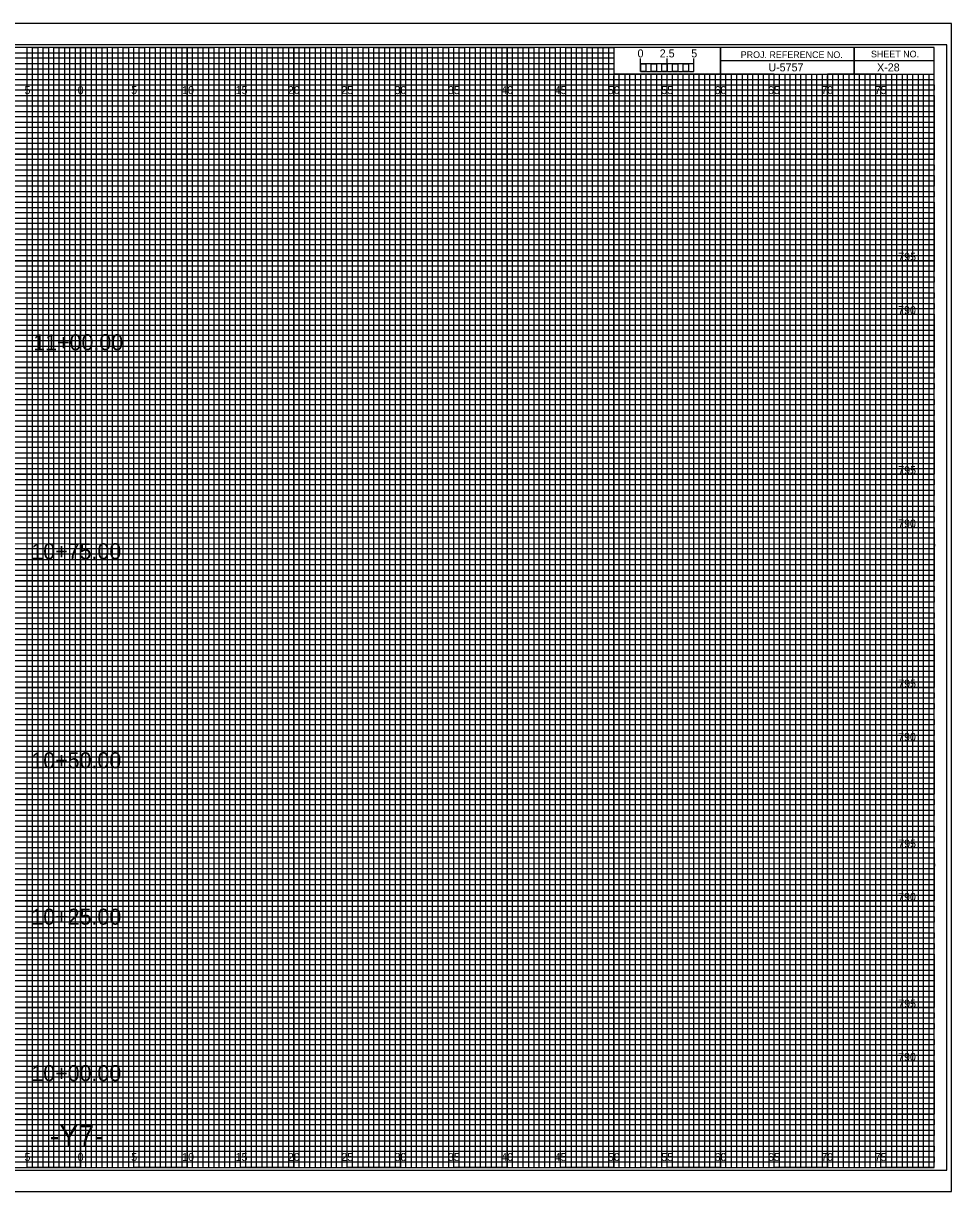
# Model space of a CAD drawing. Extents: x -7 to 162, y -2 to 107.
# Drawn here: x 74.6 to 161.7, y -2.3 to 107.3 of the extents above; entities that cross this region are included whole.
import ezdxf

# ---------------------------------------------------------------- set-up
doc = ezdxf.new("R2010")
doc.units = 0
for name, color, linetype in [('Exist Cross Section Cell', 7, 'Continuous'), ('Exist XS Center Line Elevation Label', 7, 'Continuous'), ('Prop CMT Pvmt Course 2 Wedge', 7, 'Continuous'), ('Prop XS Alignment Label', 7, 'Continuous'), ('Prop XS Bar Scale Labels', 7, 'Continuous'), ('Prop XS Elevation Labels', 7, 'Continuous'), ('Prop XS Hydro Elevations', 7, 'Continuous'), ('Prop XS Project Number', 7, 'Continuous'), ('Prop XS SE Text', 7, 'Continuous'), ('Prop XS Sheet Number', 7, 'Continuous'), ('Prop XS Side Slope Text', 7, 'Continuous'), ('Prop XS Station Labels', 7, 'Continuous'), ('Sheet Cross Section Scale CELL', 7, 'Continuous'), ('Sheet Cutting Line CELL', 7, 'Continuous'), ('Sheet DOT Grid CELL', 7, 'Continuous'), ('Sheet Plot Border Inside CELL', 7, 'Continuous'), ('Sheet Plot Border Outside CELL', 7, 'Continuous')]:
    doc.layers.add(name, color=color, linetype=linetype)

msp = doc.modelspace()

# ---------------------------------------------------------------- linework, layer by layer
at = {"layer": 'Exist Cross Section Cell'}
for p, q in [((75, 105), (70, 105)), ((75, 0), (75, 105)), ((85, 105), (80, 105)), ((80, 105), (80, 0)), ((85, 0), (85, 105)), ((95, 105), (90, 105)), ((90, 105), (90, 0)), ((95, 0), (95, 105)), ((105, 105), (100, 105)), ((100, 105), (100, 0)), ((105, 0), (105, 105)), ((115, 105), (110, 105)), ((110, 105), (110, 0)), ((115, 0), (115, 105)), ((125, 105), (120, 105)), ((120, 105), (120, 0)), ((125, 0), (125, 105)), ((130, 105), (130, 0)), ((135, 0), (135, 102.5)), ((145, 102.5), (140, 102.5)), ((140, 102.5), (140, 0)), ((145, 0), (145, 102.5)), ((155, 102.5), (150, 102.5)), ((150, 102.5), (150, 0)), ((155, 0), (155, 102.5)), ((80, 0), (75, 0)), ((90, 0), (85, 0)), ((100, 0), (95, 0)), ((110, 0), (105, 0)), ((120, 0), (115, 0)), ((130, 0), (125, 0)), ((140, 0), (135, 0)), ((150, 0), (145, 0)), ((160, 0), (155, 0)), ((160, 0), (160, 0))]:
    msp.add_line(p, q, dxfattribs=at)
for points in [[(0, 100), (160, 100), (160, 95), (0, 95)], [(0, 90), (160, 90), (160, 85), (0, 85)], [(0, 80), (160, 80), (160, 75), (0, 75)], [(0, 70), (160, 70), (160, 65), (0, 65)], [(0, 60), (160, 60), (160, 55), (0, 55)], [(0, 50), (160, 50), (160, 45), (0, 45)], [(0, 40), (160, 40), (160, 35), (0, 35)], [(0, 30), (160, 30), (160, 25), (0, 25)], [(0, 20), (160, 20), (160, 15), (0, 15)], [(0, 10), (160, 10), (160, 5), (0, 5)]]:
    msp.add_lwpolyline(points, dxfattribs=at)
at = {"layer": 'Exist XS Center Line Elevation Label'}
for points in [[(72.5, 0), (77.5, 0), (77.5, 105), (82.5, 105), (82.5, 0), (87.5, 0), (87.5, 105), (92.5, 105), (92.5, 0), (97.5, 0), (97.5, 105), (102.5, 105), (102.5, 0), (107.5, 0), (107.5, 105), (112.5, 105), (112.5, 0), (117.5, 0), (117.5, 105), (122.5, 105), (122.5, 0), (127.5, 0), (127.5, 105), (129.97, 105), (130, 105), (130, 102.5), (132.5, 102.5), (132.5, 0), (137.5, 0), (137.5, 102.5), (142.5, 102.5), (142.5, 0), (147.5, 0), (147.5, 102.5), (152.5, 102.5), (152.5, 0), (157.5, 0), (157.5, 102.5)], [(0, 102.5), (137.5, 102.5)], [(0, 92.5), (160, 92.5), (160, 97.5), (0, 97.5)], [(0, 82.5), (160, 82.5), (160, 87.5), (0, 87.5)], [(0, 72.5), (160, 72.5), (160, 77.5), (0, 77.5)], [(0, 62.5), (160, 62.5), (160, 67.5), (0, 67.5)], [(0, 52.5), (160, 52.5), (160, 57.5), (0, 57.5)], [(0, 42.5), (160, 42.5), (160, 47.5), (0, 47.5)], [(0, 32.5), (160, 32.5), (160, 37.5), (0, 37.5)], [(0, 22.5), (160, 22.5), (160, 27.5), (0, 27.5)], [(0, 12.5), (160, 12.5), (160, 17.5), (0, 17.5)], [(0, 2.5), (160, 2.5), (160, 7.5), (0, 7.5)]]:
    msp.add_lwpolyline(points, dxfattribs=at)
at = {"layer": 'Prop CMT Pvmt Course 2 Wedge'}
for p, q in [((133.5, 102.5), (133, 102.5)), ((133, 102.5), (133, 0)), ((133.5, 0), (133.5, 102.5)), ((134.5, 102.5), (134, 102.5)), ((134, 102.5), (134, 0)), ((134.5, 0), (134.5, 102.5)), ((133, 0), (132.5, 0)), ((134, 0), (133.5, 0))]:
    msp.add_line(p, q, dxfattribs=at)
for points in [[(75, 0), (75.5, 0), (75.5, 105), (76, 105), (76, 0)], [(76, 0), (76.5, 0), (76.5, 105), (77, 105), (77, 0)], [(77.5, 0), (78, 0), (78, 105), (78.5, 105), (78.5, 0)], [(78.5, 0), (79, 0), (79, 105), (79.5, 105), (79.5, 0)], [(80, 0), (80.5, 0), (80.5, 105), (81, 105), (81, 0)], [(81, 0), (81.5, 0), (81.5, 105), (82, 105), (82, 0)], [(82.5, 0), (83, 0), (83, 105), (83.5, 105), (83.5, 0)], [(83.5, 0), (84, 0), (84, 105), (84.5, 105), (84.5, 0)], [(85, 0), (85.5, 0), (85.5, 105), (86, 105), (86, 0)], [(86, 0), (86.5, 0), (86.5, 105), (87, 105), (87, 0)], [(87.5, 0), (88, 0), (88, 105), (88.5, 105), (88.5, 0)], [(88.5, 0), (89, 0), (89, 105), (89.5, 105), (89.5, 0)], [(90, 0), (90.5, 0), (90.5, 105), (91, 105), (91, 0)], [(91, 0), (91.5, 0), (91.5, 105), (92, 105), (92, 0)], [(92.5, 0), (93, 0), (93, 105), (93.5, 105), (93.5, 0)], [(93.5, 0), (94, 0), (94, 105), (94.5, 105), (94.5, 0)], [(95, 0), (95.5, 0), (95.5, 105), (96, 105), (96, 0)], [(96, 0), (96.5, 0), (96.5, 105), (97, 105), (97, 0)], [(97.5, 0), (98, 0), (98, 105), (98.5, 105), (98.5, 0)], [(98.5, 0), (99, 0), (99, 105), (99.5, 105), (99.5, 0)], [(100, 0), (100.5, 0), (100.5, 105), (101, 105), (101, 0)], [(101, 0), (101.5, 0), (101.5, 105), (102, 105), (102, 0)], [(102.5, 0), (103, 0), (103, 105), (103.5, 105), (103.5, 0)], [(103.5, 0), (104, 0), (104, 105), (104.5, 105), (104.5, 0)], [(105, 0), (105.5, 0), (105.5, 105), (106, 105), (106, 0)], [(106, 0), (106.5, 0), (106.5, 105), (107, 105), (107, 0)], [(107.5, 0), (108, 0), (108, 105), (108.5, 105), (108.5, 0)], [(108.5, 0), (109, 0), (109, 105), (109.5, 105), (109.5, 0)], [(110, 0), (110.5, 0), (110.5, 105), (111, 105), (111, 0)], [(111, 0), (111.5, 0), (111.5, 105), (112, 105), (112, 0)], [(112.5, 0), (113, 0), (113, 105), (113.5, 105), (113.5, 0)], [(113.5, 0), (114, 0), (114, 105), (114.5, 105), (114.5, 0)], [(115, 0), (115.5, 0), (115.5, 105), (116, 105), (116, 0)], [(116, 0), (116.5, 0), (116.5, 105), (117, 105), (117, 0)], [(117.5, 0), (118, 0), (118, 105), (118.5, 105), (118.5, 0)], [(118.5, 0), (119, 0), (119, 105), (119.5, 105), (119.5, 0)], [(120, 0), (120.5, 0), (120.5, 105), (121, 105), (121, 0)], [(121, 0), (121.5, 0), (121.5, 105), (122, 105), (122, 0)], [(122.5, 0), (123, 0), (123, 105), (123.5, 105), (123.5, 0)], [(123.5, 0), (124, 0), (124, 105), (124.5, 105), (124.5, 0)], [(125, 0), (125.5, 0), (125.5, 105), (126, 105), (126, 0)], [(126, 0), (126.5, 0), (126.5, 105), (127, 105), (127, 0)], [(127.5, 0), (128, 0), (128, 105), (128.5, 105), (128.5, 0)], [(128.5, 0), (129, 0), (129, 105), (129.5, 105), (129.5, 0)], [(130, 0), (130.5, 0), (130.5, 102.5), (131.01, 102.5), (131.01, 0)], [(131, 0), (131.5, 0), (131.5, 102.5), (132, 102.5), (132, 0)], [(135, 0), (135.49, 0), (135.49, 102.5), (136, 102.5), (136, 0)], [(136, 0), (136.5, 0), (136.5, 102.5), (137.03, 102.5), (137.03, 0)], [(137.5, 0), (138, 0), (138, 102.5), (138.5, 102.5), (138.5, 0)], [(138.5, 0), (139, 0), (139, 102.5), (139.5, 102.5), (139.5, 0)], [(140, 0), (140.5, 0), (140.5, 102.5), (141, 102.5), (141, 0)], [(141, 0), (141.5, 0), (141.5, 102.5), (142, 102.5), (142, 0)], [(142.5, 0), (143, 0), (143, 102.5), (143.5, 102.5), (143.5, 0)], [(143.5, 0), (144, 0), (144, 102.5), (144.5, 102.5), (144.5, 0)], [(145, 0), (145.5, 0), (145.5, 102.5), (146, 102.5), (146, 0)], [(146, 0), (146.5, 0), (146.5, 102.5), (147, 102.5), (147, 0)], [(147.5, 0), (148, 0), (148, 102.5), (148.5, 102.5), (148.5, 0)], [(148.5, 0), (149, 0), (149, 102.5), (149.5, 102.5), (149.5, 0)], [(150, 0), (150.5, 0), (150.5, 102.5), (151, 102.5), (151, 0)], [(151, 0), (151.5, 0), (151.5, 102.5), (152, 102.5), (152, 0)], [(152.5, 0), (153, 0), (153, 102.5), (153.5, 102.5), (153.5, 0)], [(153.5, 0), (154, 0), (154, 102.5), (154.5, 102.5), (154.5, 0)], [(155, 0), (155.5, 0), (155.5, 102.5), (156, 102.5), (156, 0)], [(156, 0), (156.5, 0), (156.5, 102.5), (157, 102.5), (157, 0)], [(157.5, 0), (158, 0), (158, 102.5), (158.5, 102.5), (158.5, 0)], [(158.5, 0), (159, 0), (159, 102.5), (159.5, 102.5), (159.5, 0)]]:
    msp.add_lwpolyline(points, dxfattribs=at)
at = {"layer": 'Prop XS Hydro Elevations'}
for p, q in [((152.5, 105), (152.5, 102.5)), ((152.5, 102.5), (152.5, 105)), ((160, 103.75), (140, 103.75)), ((140, 103.75), (140, 102.5)), ((140, 102.5), (160, 102.5))]:
    msp.add_line(p, q, dxfattribs=at)
for points in [[(160, 105), (0, 105), (0, 0), (160, 0)], [(140, 105), (130, 105), (130, 102.52), (140, 102.52)], [(160, 105), (140, 105), (140, 102.5), (160, 102.5)]]:
    msp.add_lwpolyline(points, close=True, dxfattribs=at)
at = {"layer": 'Prop XS Side Slope Text'}
for p, q in [((0, 104.5), (130, 104.5)), ((130, 104.5), (130, 103.99)), ((130, 103.99), (0, 103.99)), ((0, 103.5), (130, 103.5)), ((130, 102.95), (0, 102.95)), ((130, 103.5), (130, 102.95)), ((0, 102), (160, 102))]:
    msp.add_line(p, q, dxfattribs=at)
for points in [[(0, 101.5), (135, 101.5), (160, 101.5), (160, 101), (0, 101)], [(0, 100.5), (160, 100.5), (160, 99.5), (0, 99.5)], [(0, 99), (160, 99), (160, 98.5), (0, 98.49)], [(0, 98), (160, 98), (160, 97), (0, 97)], [(0, 96.5), (160, 96.5), (160, 96), (0, 96)], [(0, 95.5), (160, 95.5), (160, 94.5), (0, 94.5)], [(0, 94), (160, 94), (160, 93.5), (0, 93.5)], [(0, 93), (160, 93), (160, 92), (0, 92)], [(0, 91.5), (160, 91.5), (160, 91), (0, 91)], [(0, 90.5), (160, 90.5), (160, 89.5), (0, 89.5)], [(0, 89), (160, 89), (160, 88.5), (0, 88.5)], [(0, 88), (160, 88), (160, 86.98), (160, 86.5), (160, 86), (0, 86)], [(0, 87), (160, 87), (160, 86.5), (0, 86.5)], [(0, 85.5), (160, 85.5), (160, 84.5), (0, 84.52)], [(0, 84.52), (160, 84.5), (160, 84), (0, 84)], [(0, 83.5), (160, 83.5), (160, 83), (0, 83)], [(0, 82), (160, 82), (160, 81.5), (0, 81.5)], [(0, 81), (160, 81), (160, 80.5), (0, 80.5)], [(-0.04, 79.45), (160, 79.45), (160, 78.94), (-0.04, 78.94)], [(0, 78.5), (160, 78.5), (160, 78), (0, 78)], [(0, 77), (160, 77), (160, 76.5), (0, 76.5)], [(0, 76), (160, 76), (160, 75.5), (0, 75.5)], [(0, 74.5), (160, 74.5), (160, 74), (0, 74)], [(0, 73.5), (160, 73.5), (160, 73), (0, 73)], [(0, 72), (160, 72), (160, 71.5), (0, 71.5)], [(0, 71), (160, 71), (160, 70.5), (0, 70.5)], [(0, 69.5), (160, 69.5), (160, 68.99), (0, 69)], [(0, 68.5), (160, 68.5), (160, 68), (0, 68)], [(0, 67), (160, 67), (160, 66.5), (0, 66.5)], [(0, 66), (160, 66), (160, 65.5), (0, 65.5)], [(0, 64.5), (160, 64.5), (160, 64), (0, 64)], [(0, 63.5), (160, 63.5), (160, 63), (0, 63)], [(0, 62), (160, 62), (160, 61.5), (0, 61.5)], [(0, 61), (160, 61), (160, 60.5), (0, 60.5)], [(0, 59.5), (160, 59.5), (160, 59), (0, 59)], [(0, 58.5), (160.03, 58.45), (160, 58), (0, 58)], [(0, 57), (160, 57), (160, 56.5), (0, 56.5)], [(0, 56), (160, 56), (160, 55.5), (0, 55.5)], [(0, 54.5), (160, 54.5), (160, 54), (0, 54)], [(0, 53.5), (160, 53.5), (160, 53), (0, 53)], [(0, 52), (160, 52), (160, 51.5), (0, 51.5)], [(0, 51), (160, 51), (160, 50.5), (0, 50.5)], [(0, 49.5), (160, 49.5), (160, 49), (0, 49)], [(0, 48.5), (160, 48.5), (160, 48), (0, 48)], [(0, 47), (160, 47), (160, 46.5), (0, 46.5)], [(0, 46), (160, 46), (160, 45.5), (0, 45.5)], [(0, 44.5), (160, 44.5), (160, 44), (0, 44)], [(0, 43.5), (160, 43.5), (160, 43), (0, 43)], [(0, 42), (160, 42), (160, 41.5), (0, 41.5)], [(0, 41), (160, 41), (160, 40.5), (0, 40.5)], [(0, 39.5), (160, 39.5), (160, 38.99), (0, 39)], [(0, 38.5), (160, 38.5), (160, 38), (0, 38)], [(0, 37), (160, 37), (160, 36.5), (0, 36.5)], [(0, 36), (160, 36), (160, 35.5), (0, 35.5)], [(0, 34.5), (160, 34.5), (160, 34), (0, 34)], [(0, 33.5), (160, 33.5), (160, 33), (0, 33)], [(0, 32), (160, 32), (160, 31.5), (0, 31.5)], [(0, 31), (160, 31), (160, 30.5), (0, 30.5)], [(0, 29.5), (160, 29.5), (160, 29), (0, 29)], [(0, 28.5), (160.03, 28.46), (160, 28), (0, 28)], [(0, 27), (160, 27), (160, 26.5), (0, 26.5)], [(0, 26), (160, 26), (160, 25.5), (0, 25.5)], [(0, 24.5), (160, 24.5), (160, 24), (0, 24)], [(0, 23.5), (160, 23.5), (160, 23), (0, 23)], [(0, 22), (160, 22), (160, 21.5), (0, 21.5)], [(0, 21), (160, 21), (160, 20.5), (0, 20.5)], [(0, 19.5), (160, 19.5), (160, 19), (0, 19)], [(0, 18.5), (160, 18.5), (160, 18), (0, 18)], [(0, 17), (160, 17), (160, 16.5), (0, 16.5)], [(0, 16), (160, 16), (160, 15.5), (0, 15.5)], [(0, 14.5), (160, 14.5), (160, 14), (0, 14)], [(0, 13.5), (160, 13.5), (160, 13), (0, 13)], [(0, 12), (160, 12), (160, 11.5), (0, 11.5)], [(0, 11), (160, 11), (160, 10.5), (0, 10.5)], [(0, 9.5), (160, 9.5), (160, 9), (0, 9)], [(0, 8.5), (160, 8.5), (160, 8), (0, 8)], [(0, 7), (160, 7), (160, 6.5), (0, 6.5)], [(0, 6), (160, 6), (160, 5.5), (0, 5.5)], [(0, 4.5), (160, 4.5), (160, 4), (0, 4)], [(0, 3.5), (160, 3.5), (160, 3), (0, 3)], [(0, 2), (160, 2), (160, 1.5), (0, 1.5)], [(0, 1), (160, 1), (160, 0.5), (0, 0.5)]]:
    msp.add_lwpolyline(points, dxfattribs=at)
at = {"layer": 'Sheet Cross Section Scale CELL'}
for p, q in [((132.5, 102.75), (132.5, 103.95)), ((132.5, 103.45), (132.5, 103.95)), ((135, 102.75), (135, 103.95)), ((137.5, 102.75), (137.5, 103.95)), ((137.5, 103.45), (137.5, 103.95))]:
    msp.add_line(p, q, dxfattribs=at)
for points in [[(137.5, 103.45), (132.5, 103.45), (132.5, 102.75), (137.5, 102.75)], [(132.5, 103.45), (133, 103.45), (133, 102.75), (132.5, 102.75)], [(133.5, 103.45), (134, 103.45), (134, 102.75), (133.5, 102.75)], [(134.5, 103.45), (135, 103.45), (135, 102.75), (134.5, 102.75)], [(135.5, 103.45), (136, 103.45), (136, 102.75), (135.5, 102.75)], [(136.5, 103.45), (137, 103.45), (137, 102.75), (136.5, 102.75)]]:
    msp.add_lwpolyline(points, close=True, dxfattribs=at)
at = {"layer": 'Sheet Cutting Line CELL'}
for p, q in [((161.65, 107.25), (-6.7, 107.25)), ((-6.7, -2.25), (161.65, -2.25))]:
    msp.add_line(p, q, dxfattribs=at)
at = {"layer": 'Sheet DOT Grid CELL'}
for p, q in [((75, 0), (75, 105)), ((80, 0), (80, 105)), ((85, 0), (85, 105)), ((90, 0), (90, 105)), ((95, 0), (95, 105)), ((100, 0), (100, 105)), ((105, 0), (105, 105)), ((110, 0), (110, 105)), ((115, 0), (115, 105)), ((120, 0), (120, 105)), ((125, 0), (125, 105)), ((130, 0), (130, 102.34)), ((135, 0), (135, 102.34)), ((140, 0), (140, 102.34)), ((145, 0), (145, 102.34)), ((150, 0), (150, 102.34)), ((155, 0), (155, 102.34)), ((0, 100), (160, 100)), ((0, 95), (160, 95)), ((0, 90), (160, 90)), ((0, 85), (160, 85)), ((0, 80), (160, 80)), ((0, 75), (160, 75)), ((0, 70), (160, 70)), ((0, 65), (160, 65)), ((0, 60), (160, 60)), ((0, 55), (160, 55)), ((0, 50), (160, 50)), ((0, 45), (160, 45)), ((0, 40), (160, 40)), ((0, 35), (160, 35)), ((0, 30), (160, 30)), ((0, 25), (160, 25)), ((0, 20), (160, 20)), ((0, 15), (160, 15)), ((0, 10), (160, 10)), ((0, 5), (160, 5))]:
    msp.add_line(p, q, dxfattribs=at)
at = {"layer": 'Sheet Plot Border Inside CELL'}
msp.add_lwpolyline([(-5.4, -0.25), (161.2, -0.25), (161.2, 105.25), (-5.4, 105.25)], close=True, dxfattribs=at)
at = {"layer": 'Sheet Plot Border Outside CELL'}
msp.add_lwpolyline([(-6.7, -2.25), (161.65, -2.25), (161.65, 107.25), (-6.7, 107.25)], close=True, dxfattribs=at)

# ---------------------------------------------------------------- texts
at = {"layer": 'Prop XS Alignment Label'}
msp.add_text('-Y7-', height=2, dxfattribs=at).set_placement((77.12, 2))
at = {"layer": 'Prop XS Bar Scale Labels'}
for s, p in [('2.5', (134.29, 104.06)), ('5', (137.24, 104.06))]:
    msp.add_text(s, height=0.75, dxfattribs=at).set_placement(p)
at = {"layer": 'Prop XS Elevation Labels'}
for s, p in [('795', (156.64, 85)), ('790', (156.63, 80)), ('795', (156.64, 65)), ('790', (156.63, 60)), ('795', (156.64, 45)), ('790', (156.63, 40)), ('795', (156.64, 30)), ('790', (156.63, 25)), ('795', (156.64, 15)), ('790', (156.63, 10))]:
    msp.add_text(s, height=0.75, dxfattribs=at).set_placement(p)
at = {"layer": 'Prop XS Hydro Elevations'}
for s, p in [('PROJ. REFERENCE NO.', (141.88, 104)), ('SHEET NO.', (154.09, 104.06))]:
    msp.add_text(s, height=0.625, dxfattribs=at).set_placement(p)
at = {"layer": 'Prop XS Project Number'}
msp.add_text('U-5757', height=0.75, dxfattribs=at).set_placement((144.47, 102.75))
at = {"layer": 'Prop XS SE Text'}
for s, p in [('5', (74.74, 100.62)), ('0', (79.73, 100.62)), ('0', (79.73, 100.62)), ('5', (84.74, 100.62)), ('10', (89.52, 100.62)), ('15', (94.53, 100.62)), ('20', (99.43, 100.62)), ('25', (104.44, 100.62)), ('30', (109.43, 100.62)), ('35', (114.44, 100.62)), ('40', (119.43, 100.62)), ('45', (124.44, 100.62)), ('50', (129.43, 100.62)), ('55', (134.44, 100.62)), ('60', (139.43, 100.62)), ('65', (144.44, 100.62)), ('70', (149.43, 100.62)), ('75', (154.44, 100.62)), ('5', (74.74, 0.62)), ('0', (79.73, 0.62)), ('0', (79.73, 0.62)), ('5', (84.74, 0.62)), ('10', (89.52, 0.62)), ('15', (94.53, 0.62)), ('20', (99.43, 0.62)), ('25', (104.44, 0.62)), ('30', (109.43, 0.62)), ('35', (114.44, 0.62)), ('40', (119.43, 0.62)), ('45', (124.44, 0.62)), ('50', (129.43, 0.62)), ('55', (134.44, 0.62)), ('60', (139.43, 0.62)), ('65', (144.44, 0.62)), ('70', (149.43, 0.62)), ('75', (154.44, 0.62))]:
    msp.add_text(s, height=0.75, dxfattribs=at).set_placement(p)
at = {"layer": 'Prop XS Sheet Number'}
msp.add_text('X-28', height=0.75, dxfattribs=at).set_placement((154.66, 102.75))
at = {"layer": 'Prop XS Station Labels'}
for s, p in [('11+00.00', (75.57, 76.61)), ('10+75.00', (75.39, 57.02)), ('10+50.00', (75.39, 37.43)), ('10+25.00', (75.39, 22.77)), ('10+00.00', (75.39, 8.11))]:
    msp.add_text(s, height=1.5, dxfattribs=at).set_placement(p)
at = {"layer": 'Sheet Cross Section Scale CELL'}
msp.add_text('0', height=0.75, dxfattribs=at).set_placement((132.21, 104.06))

doc.saveas('drawing.dxf')
